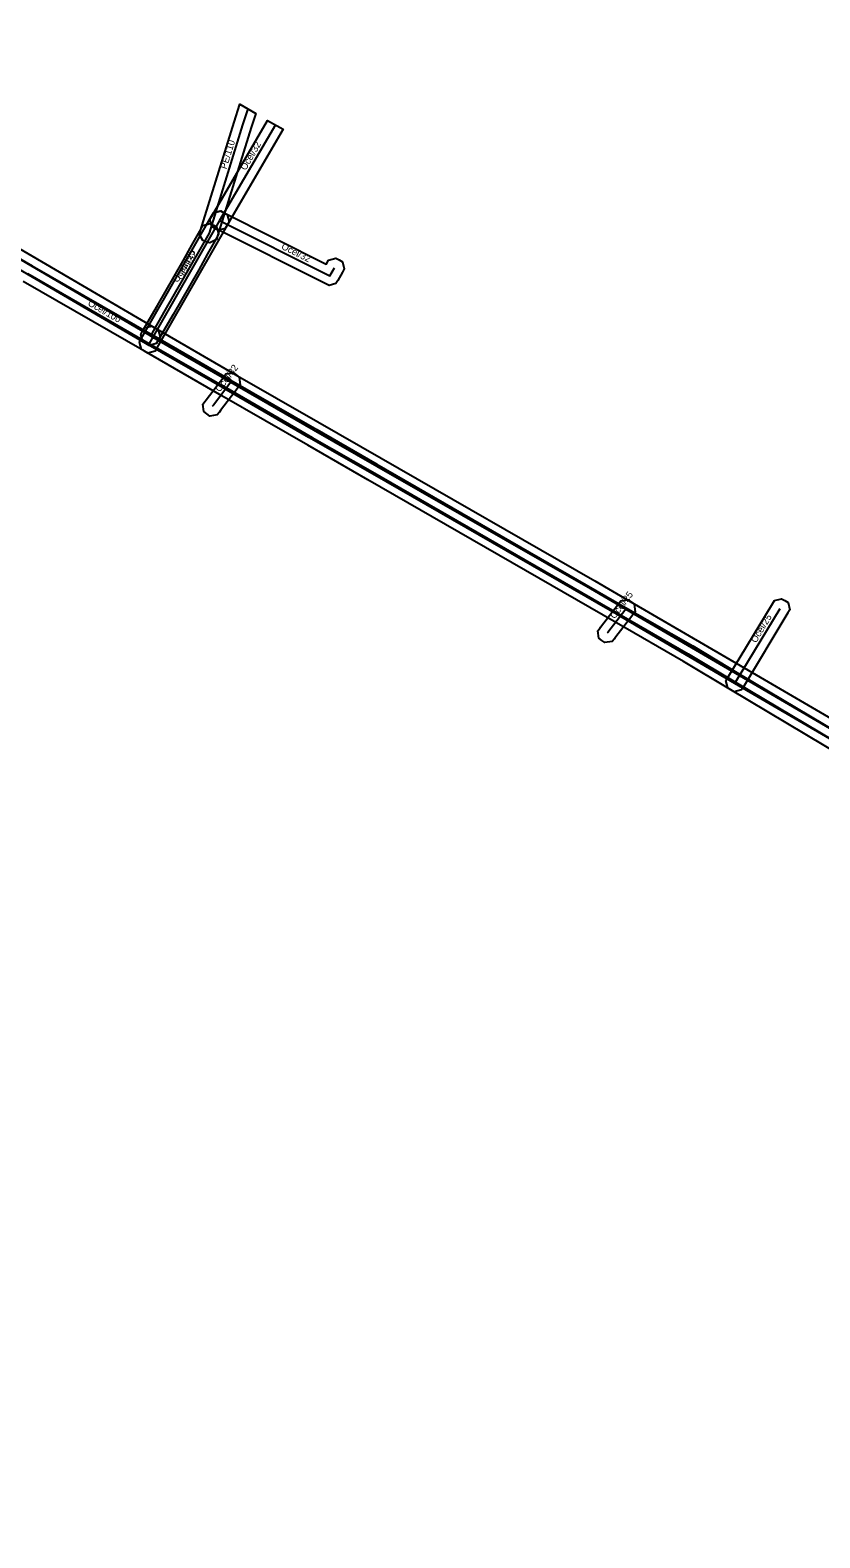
# Model space of a CAD drawing. Extents: x -749340 to -748632, y -965391 to -964902.
# Drawn here: x -748982.7 to -748895.1, y -965251.4 to -965084.1 of the extents above; entities that cross this region are included whole.
import ezdxf

# ---------------------------------------------------------------- set-up
doc = ezdxf.new("R2010")
doc.units = 0
for name, color, linetype in [('1', 7, 'Continuous'), ('18', 7, 'Continuous'), ('20', 7, 'Continuous'), ('24', 7, 'Continuous'), ('28', 7, 'Continuous'), ('30', 7, 'Continuous')]:
    doc.layers.add(name, color=color, linetype=linetype)

msp = doc.modelspace()

# ---------------------------------------------------------------- linework, layer by layer
at = {"layer": '1'}
for points in [[(-748969.52, -965119.09), (-748969.88, -965118.88), (-748998.11, -965102.38), (-749008.77, -965096.15), (-749025.51, -965086.05), (-749025.86, -965085.84), (-749026.06, -965085.03), (-749025.85, -965084.68), (-749025.63, -965084.32), (-749024.83, -965084.12), (-749024.47, -965084.34), (-749007.75, -965094.43), (-748997.1, -965100.66), (-748968.87, -965117.16), (-748968.51, -965117.37), (-748968.3, -965118.17), (-748968.51, -965118.53), (-748968.72, -965118.88)], [(-748960.09, -965094.34), (-748959.46, -965092.35), (-748957.69, -965093.37), (-748958.19, -965094.94), (-748961.91, -965106.94), (-748962.04, -965107.33), (-748962.77, -965107.72), (-748963.17, -965107.59), (-748963.56, -965107.47), (-748963.95, -965106.74), (-748963.82, -965106.34)], [(-748962.57, -965104.74), (-748956.36, -965094.13), (-748954.63, -965095.12), (-748960.85, -965105.75), (-748961.06, -965106.11), (-748961.86, -965106.32), (-748962.22, -965106.11), (-748962.57, -965105.9), (-748962.78, -965105.1)], [(-748960.64, -965105.38), (-748960.84, -965105.74), (-748968.66, -965119.37), (-748968.86, -965119.73), (-748969.66, -965119.94), (-748970.02, -965119.74), (-748970.38, -965119.53), (-748970.6, -965118.73), (-748970.39, -965118.37), (-748962.58, -965104.75), (-748962.37, -965104.39), (-748961.57, -965104.17), (-748961.21, -965104.38), (-748960.85, -965104.58)], [(-748961.63, -965104.17), (-748961.26, -965104.35), (-748949.85, -965110.07), (-748949.8, -965109.98), (-748949.59, -965109.62), (-748948.79, -965109.4), (-748948.43, -965109.6), (-748948.07, -965109.81), (-748947.85, -965110.61), (-748948.06, -965110.97), (-748948.58, -965111.88), (-748948.78, -965112.23), (-748949.54, -965112.46), (-748949.9, -965112.28), (-748962.16, -965106.14), (-748962.53, -965105.95), (-748962.79, -965105.17), (-748962.6, -965104.8), (-748962.42, -965104.43)], [(-748961.8, -965106.77), (-748962, -965107.13), (-748963.02, -965108.95), (-748964.01, -965110.71), (-748966.86, -965115.66), (-748968.51, -965118.52), (-748968.71, -965118.88), (-748969.51, -965119.09), (-748969.87, -965118.89), (-748970.23, -965118.68), (-748970.45, -965117.88), (-748970.24, -965117.52), (-748968.59, -965114.66), (-748965.75, -965109.71), (-748964.76, -965107.97), (-748963.74, -965106.15), (-748963.54, -965105.79), (-748962.74, -965105.57), (-748962.38, -965105.77), (-748962.02, -965105.97)], [(-748959.4, -965123.45), (-748959.65, -965123.77), (-748961.59, -965126.32), (-748961.72, -965126.48), (-748961.97, -965126.81), (-748962.79, -965126.93), (-748963.12, -965126.67), (-748963.45, -965126.42), (-748963.56, -965125.6), (-748963.31, -965125.27), (-748963.19, -965125.11), (-748961.24, -965122.56), (-748960.99, -965122.23), (-748960.17, -965122.12), (-748959.84, -965122.37), (-748959.51, -965122.62)], [(-748905.49, -965156.27), (-748905.27, -965155.92), (-748900.33, -965147.74), (-748900.11, -965147.39), (-748899.31, -965147.19), (-748898.96, -965147.4), (-748898.6, -965147.62), (-748898.4, -965148.42), (-748898.62, -965148.77), (-748903.56, -965156.95), (-748903.78, -965157.31), (-748904.58, -965157.51), (-748904.93, -965157.29), (-748905.29, -965157.08)], [(-748915.58, -965148.63), (-748915.83, -965148.96), (-748917.81, -965151.55), (-748917.87, -965151.62), (-748918.12, -965151.95), (-748918.95, -965152.06), (-748919.28, -965151.81), (-748919.6, -965151.56), (-748919.71, -965150.74), (-748919.46, -965150.41), (-748919.4, -965150.33), (-748917.42, -965147.74), (-748917.17, -965147.41), (-748916.34, -965147.3), (-748916.02, -965147.55), (-748915.69, -965147.81)]]:
    msp.add_lwpolyline(points, close=True, dxfattribs=at)
for points in [[(-748997.7, -965101.46), (-748982.49, -965110.26), (-748969.03, -965118), (-748960.43, -965122.95), (-748950.92, -965128.42), (-748944.23, -965132.27), (-748916.63, -965148.15), (-748909.18, -965152.43), (-748903.91, -965155.58), (-748891.49, -965162.98), (-748877.84, -965170.71), (-748866.16, -965178.84), (-748846.84, -965191.26), (-748845.3, -965192.43), (-748844.32, -965193.17), (-748827.15, -965206.19), (-748824.19, -965208.44), (-748797.89, -965228.31)], [(-748799.1, -965229.9), (-748825.4, -965210.03), (-748828.36, -965207.78), (-748845.53, -965194.76), (-748846.5, -965194.02), (-748847.98, -965192.9), (-748867.27, -965180.5), (-748878.9, -965172.41), (-748892.49, -965164.71), (-748904.93, -965157.3), (-748910.19, -965154.16), (-748917.63, -965149.88), (-748945.23, -965134), (-748951.91, -965130.16), (-748961.43, -965124.68), (-748970.03, -965119.74), (-748983.49, -965111.99)], [(-748882.98, -965169.12), (-748904.49, -965156.58), (-748917.13, -965149.21), (-748921.04, -965146.93), (-748944.74, -965133.35), (-748951.78, -965129.32), (-748960.94, -965124.03), (-748969.87, -965118.89), (-748970.23, -965118.68), (-748970.45, -965117.88), (-748970.24, -965117.52), (-748970.03, -965117.16), (-748969.23, -965116.95), (-748968.87, -965117.16), (-748959.95, -965122.3), (-748950.78, -965127.58), (-748943.75, -965131.61), (-748920.04, -965145.2), (-748916.12, -965147.48), (-748903.48, -965154.85), (-748881.97, -965167.4)]]:
    msp.add_lwpolyline(points, dxfattribs=at)
at = {"layer": '18'}
for points in [[(-748955.5, -965094.62), (-748961.71, -965105.25)], [(-748961.71, -965105.25), (-748969.53, -965118.87)], [(-748961.71, -965105.25), (-748949.45, -965111.39), (-748948.93, -965110.47)], [(-748982.99, -965111.13), (-748969.53, -965118.87), (-748960.93, -965123.81), (-748951.42, -965129.29), (-748944.73, -965133.13), (-748917.13, -965149.01), (-748909.68, -965153.3), (-748904.42, -965156.44), (-748891.99, -965163.85), (-748878.37, -965171.56), (-748866.71, -965179.67), (-748847.41, -965192.08), (-748845.9, -965193.22), (-748844.92, -965193.96), (-748827.76, -965206.98), (-748824.79, -965209.23), (-748798.49, -965229.11)], [(-748904.42, -965156.44), (-748899.47, -965148.26)]]:
    msp.add_lwpolyline(points, dxfattribs=at)
at = {"layer": '24'}
for points in [[(-748958.57, -965092.86), (-748959.14, -965094.64), (-748962.87, -965106.64)], [(-748962.87, -965106.64), (-748963.89, -965108.46), (-748964.88, -965110.21), (-748967.73, -965115.16), (-748969.37, -965118.02)]]:
    msp.add_lwpolyline(points, dxfattribs=at)
at = {"layer": '28'}
for points in [[(-748969.37, -965118.02), (-748997.61, -965101.52), (-749008.26, -965095.29), (-749024.99, -965085.2)], [(-748969.37, -965118.02), (-748960.45, -965123.17), (-748951.28, -965128.45), (-748944.25, -965132.48), (-748920.54, -965146.06), (-748916.62, -965148.35), (-748903.99, -965155.72), (-748882.47, -965168.26), (-748877.9, -965170.98), (-748844.57, -965193.37), (-748827.36, -965206.4), (-748823.66, -965209.42), (-748816.65, -965214.51), (-748766.66, -965251.35)], [(-748960.45, -965123.17), (-748962.39, -965125.72), (-748962.51, -965125.88)], [(-748916.62, -965148.35), (-748918.61, -965150.94), (-748918.67, -965151.02)]]:
    msp.add_lwpolyline(points, dxfattribs=at)

# ---------------------------------------------------------------- texts
at = {"layer": '20'}
for s, rotation, p in [('Ocel/32', 59.6642, (-748958.8, -965099.74)), ('Ocel/32', 60.1606, (-748965.84, -965111.9)), ('Ocel/32', 333.4032, (-748954.91, -965108.35)), ('Ocel/100', 330.0917, (-748976.39, -965114.61)), ('Ocel/25', 58.8481, (-748902.15, -965152.15))]:
    msp.add_text(s, height=0.75, rotation=rotation, dxfattribs=at).set_placement(p)
at = {"layer": '30'}
for s, rotation, p in [('PE/110', 72.7374, (-748960.94, -965099.59)), ('Ocel/125', 60.0946, (-748966.33, -965112.18)), ('Ocel/32', 52.6548, (-748961.68, -965124.32)), ('Ocel/25', 52.5438, (-748917.85, -965149.48))]:
    msp.add_text(s, height=0.75, rotation=rotation, dxfattribs=at).set_placement(p)

doc.saveas('drawing.dxf')
